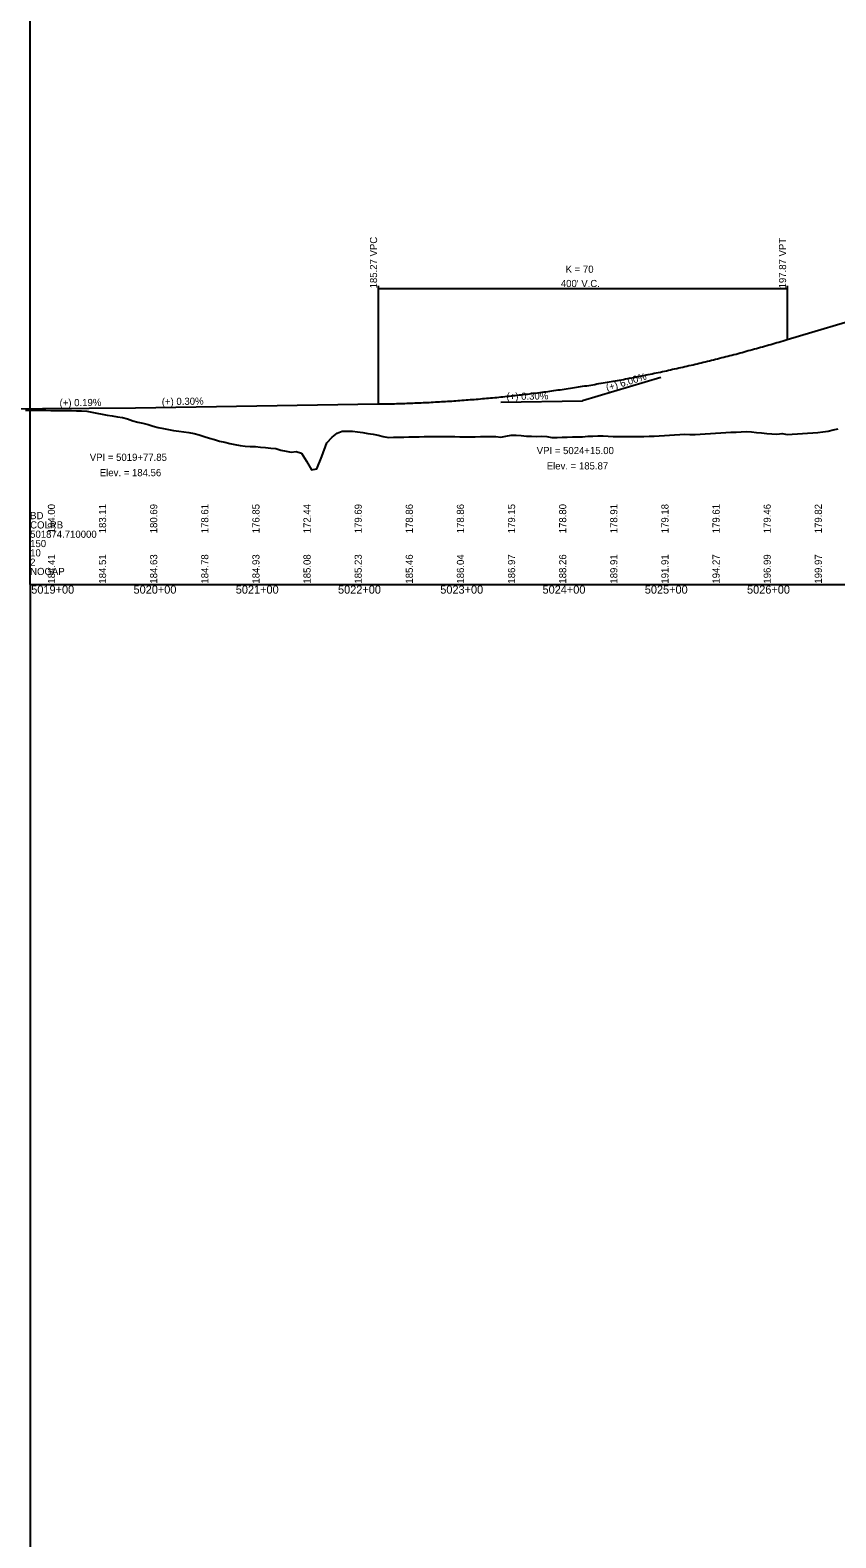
# Model space of a CAD drawing. Extents: x 1876258 to 1932803, y 754739 to 837911.
# Drawn here: x 1914544 to 1915332, y 787057 to 788531 of the extents above; entities that cross this region are included whole.
import ezdxf

# ---------------------------------------------------------------- set-up
doc = ezdxf.new("R2010")
doc.units = 0
for name, color, linetype in [('RD_DDB_GradeTX', 7, 'Continuous'), ('RD_DDB_Profile_EX', 7, 'Continuous'), ('RD_DDB_Profile_Lbl', 7, 'Continuous'), ('RD_DDB_Profile_PR', 7, 'Continuous'), ('RD_DDB_StaTX', 7, 'Continuous'), ('RD_DDB_StripGrade', 7, 'Continuous'), ('RD_DDB_VCLbl', 7, 'Continuous'), ('RD_GPK_Profile_Cell', 7, 'Continuous')]:
    doc.layers.add(name, color=color, linetype=linetype)

msp = doc.modelspace()

# ---------------------------------------------------------------- linework, layer by layer
at = {"layer": 'RD_DDB_GradeTX'}
for p in [(1915160.9, 788191.5), (1915004.3, 788167.3)]:
    msp.add_line(p, (1915084.3, 788168.5), dxfattribs=at)
at = {"layer": 'RD_DDB_Profile_EX'}
for points in [[(1914539.3, 788159.6), (1914544.3, 788159.6), (1914549.3, 788159.5), (1914554.3, 788159.5), (1914559.3, 788159.4), (1914564.3, 788159.2), (1914569.3, 788159.2), (1914574.3, 788159.1), (1914579.3, 788159), (1914584.3, 788159), (1914589.3, 788158.9), (1914594.3, 788158.8), (1914599.3, 788158.5), (1914604.3, 788157.6), (1914609.3, 788156.5), (1914614.3, 788155.6), (1914619.3, 788154.7), (1914624.3, 788154), (1914629.3, 788153.1), (1914634.3, 788152.2), (1914639.3, 788150.9), (1914644.3, 788149.1), (1914649.3, 788147.9), (1914654.3, 788146.8), (1914659.3, 788145.4), (1914664.3, 788143.8), (1914669.3, 788142.6), (1914674.3, 788141.5), (1914679.3, 788140.5), (1914684.3, 788139.7), (1914689.3, 788139), (1914694.3, 788138.3), (1914699.3, 788137.6), (1914704.3, 788136.6), (1914709.3, 788135.2), (1914714.3, 788133.7), (1914719.3, 788132.2), (1914724.3, 788130.7), (1914729.3, 788129.2), (1914734.3, 788128.1), (1914739.3, 788127), (1914744.3, 788126), (1914749.3, 788124.9), (1914754.3, 788124.2), (1914759.3, 788123.9), (1914764.3, 788123.9), (1914769.3, 788123.4), (1914774.3, 788122.9), (1914779.3, 788122.4), (1914784.3, 788121.9), (1914789.3, 788120.5), (1914794.3, 788119.5), (1914799.3, 788118.5), (1914804.3, 788119.1), (1914809.3, 788117.5), (1914814.3, 788109.7), (1914819.3, 788101.3), (1914824.3, 788102.2), (1914829.3, 788114.1), (1914834.3, 788127.5), (1914839.3, 788133.2), (1914844.3, 788136.9), (1914849.3, 788139.1), (1914854.3, 788139), (1914859.3, 788138.9), (1914864.3, 788138.4), (1914869.3, 788137.6), (1914874.3, 788136.8), (1914879.3, 788136), (1914884.3, 788135.1), (1914889.3, 788133.7), (1914894.3, 788132.9), (1914899.3, 788133), (1914904.3, 788133.1), (1914909.3, 788133.2), (1914914.3, 788133.3), (1914919.3, 788133.4), (1914924.3, 788133.5), (1914929.3, 788133.6), (1914934.3, 788133.6), (1914939.3, 788133.6), (1914944.3, 788133.7), (1914949.3, 788133.7), (1914954.3, 788133.7), (1914959.3, 788133.6), (1914964.3, 788133.4)], [(1914539.3, 788159.6), (1914544.3, 788159.6), (1914549.3, 788159.5), (1914554.3, 788159.5), (1914559.3, 788159.4), (1914564.3, 788159.2), (1914569.3, 788159.2), (1914574.3, 788159.1), (1914579.3, 788159), (1914584.3, 788159), (1914589.3, 788158.9), (1914594.3, 788158.8), (1914599.3, 788158.5), (1914604.3, 788157.6), (1914609.3, 788156.5), (1914614.3, 788155.6), (1914619.3, 788154.7), (1914624.3, 788154), (1914629.3, 788153.1), (1914634.3, 788152.2), (1914639.3, 788150.9), (1914644.3, 788149.1), (1914649.3, 788147.9), (1914654.3, 788146.8), (1914659.3, 788145.4), (1914664.3, 788143.8), (1914669.3, 788142.6), (1914674.3, 788141.5), (1914679.3, 788140.5), (1914684.3, 788139.7), (1914689.3, 788139), (1914694.3, 788138.3), (1914699.3, 788137.6), (1914704.3, 788136.6), (1914709.3, 788135.2), (1914714.3, 788133.7), (1914719.3, 788132.2), (1914724.3, 788130.7), (1914729.3, 788129.2), (1914734.3, 788128.1), (1914739.3, 788127), (1914744.3, 788126), (1914749.3, 788124.9), (1914754.3, 788124.2), (1914759.3, 788123.9), (1914764.3, 788123.9), (1914769.3, 788123.4), (1914774.3, 788122.9), (1914779.3, 788122.4), (1914784.3, 788121.9), (1914789.3, 788120.5), (1914794.3, 788119.5), (1914799.3, 788118.5), (1914804.3, 788119.1), (1914809.3, 788117.5), (1914814.3, 788109.7), (1914819.3, 788101.3), (1914824.3, 788102.2), (1914829.3, 788114.1), (1914834.3, 788127.5), (1914839.3, 788133.2), (1914844.3, 788136.9), (1914849.3, 788139.1), (1914854.3, 788139), (1914859.3, 788138.9), (1914864.3, 788138.4), (1914869.3, 788137.6), (1914874.3, 788136.8), (1914879.3, 788136), (1914884.3, 788135.1), (1914889.3, 788133.7), (1914894.3, 788132.9), (1914899.3, 788133), (1914904.3, 788133.1), (1914909.3, 788133.2), (1914914.3, 788133.3), (1914919.3, 788133.4), (1914924.3, 788133.5), (1914929.3, 788133.6), (1914934.3, 788133.6), (1914939.3, 788133.6), (1914944.3, 788133.7), (1914949.3, 788133.7), (1914954.3, 788133.7), (1914959.3, 788133.6), (1914964.3, 788133.4)], [(1914964.3, 788133.4), (1914969.3, 788133.4), (1914974.3, 788133.5), (1914979.3, 788133.5), (1914984.3, 788133.6), (1914989.3, 788133.7), (1914994.3, 788133.8), (1914999.3, 788133.6), (1915004.3, 788133.1), (1915009.3, 788134.1), (1915014.3, 788135), (1915019.3, 788134.9), (1915024.3, 788134.8), (1915029.3, 788134.1), (1915034.3, 788133.9), (1915039.3, 788133.8), (1915044.3, 788133.9), (1915049.3, 788133.7), (1915054.3, 788132.6), (1915059.3, 788132.7), (1915064.3, 788133), (1915069.3, 788133.1), (1915074.3, 788133.3), (1915079.3, 788133.4), (1915084.3, 788133.5), (1915089.3, 788134.1), (1915094.3, 788134.2), (1915099.3, 788134.3), (1915104.3, 788134.3), (1915109.3, 788134.1), (1915114.3, 788133.7), (1915119.3, 788133.7), (1915124.3, 788133.7), (1915129.3, 788133.7), (1915134.3, 788133.6), (1915139.3, 788133.7), (1915144.3, 788133.7), (1915149.3, 788134), (1915154.3, 788134.2), (1915159.3, 788134.5), (1915164.3, 788134.8), (1915169.3, 788135.1), (1915174.3, 788135.3), (1915179.3, 788135.6), (1915184.3, 788135.9), (1915189.3, 788135.6), (1915194.3, 788135.8), (1915199.3, 788136.1), (1915204.3, 788136.4), (1915209.3, 788136.7), (1915214.3, 788136.9), (1915219.3, 788137.2), (1915224.3, 788137.5), (1915229.3, 788137.8), (1915234.3, 788138), (1915239.3, 788138.3), (1915244.3, 788138.6), (1915249.3, 788138.2), (1915254.3, 788137.6), (1915259.3, 788137.2), (1915264.3, 788136.8), (1915269.3, 788136.4), (1915274.3, 788136.1), (1915279.3, 788136.8), (1915284.3, 788135.7), (1915289.3, 788136), (1915294.3, 788136.3), (1915299.3, 788136.6), (1915304.3, 788136.9), (1915309.3, 788137.2), (1915314.3, 788137.5), (1915319.3, 788138.2), (1915324.3, 788138.9), (1915329.3, 788140.1), (1915334.3, 788141.2)], [(1914964.3, 788133.4), (1914969.3, 788133.4), (1914974.3, 788133.5), (1914979.3, 788133.5), (1914984.3, 788133.6), (1914989.3, 788133.7), (1914994.3, 788133.8), (1914999.3, 788133.6), (1915004.3, 788133.1), (1915009.3, 788134.1), (1915014.3, 788135), (1915019.3, 788134.9), (1915024.3, 788134.8), (1915029.3, 788134.1), (1915034.3, 788133.9), (1915039.3, 788133.8), (1915044.3, 788133.9), (1915049.3, 788133.7), (1915054.3, 788132.6), (1915059.3, 788132.7), (1915064.3, 788133), (1915069.3, 788133.1), (1915074.3, 788133.3), (1915079.3, 788133.4), (1915084.3, 788133.5), (1915089.3, 788134.1), (1915094.3, 788134.2), (1915099.3, 788134.3), (1915104.3, 788134.3), (1915109.3, 788134.1), (1915114.3, 788133.7), (1915119.3, 788133.7), (1915124.3, 788133.7), (1915129.3, 788133.7), (1915134.3, 788133.6), (1915139.3, 788133.7), (1915144.3, 788133.7), (1915149.3, 788134), (1915154.3, 788134.2), (1915159.3, 788134.5), (1915164.3, 788134.8), (1915169.3, 788135.1), (1915174.3, 788135.3), (1915179.3, 788135.6), (1915184.3, 788135.9), (1915189.3, 788135.6), (1915194.3, 788135.8), (1915199.3, 788136.1), (1915204.3, 788136.4), (1915209.3, 788136.7), (1915214.3, 788136.9), (1915219.3, 788137.2), (1915224.3, 788137.5), (1915229.3, 788137.8), (1915234.3, 788138), (1915239.3, 788138.3), (1915244.3, 788138.6), (1915249.3, 788138.2), (1915254.3, 788137.6), (1915259.3, 788137.2), (1915264.3, 788136.8), (1915269.3, 788136.4), (1915274.3, 788136.1), (1915279.3, 788136.8), (1915284.3, 788135.7), (1915289.3, 788136), (1915294.3, 788136.3), (1915299.3, 788136.6), (1915304.3, 788136.9), (1915309.3, 788137.2), (1915314.3, 788137.5), (1915319.3, 788138.2), (1915324.3, 788138.9), (1915329.3, 788140.1), (1915334.3, 788141.2)]]:
    msp.add_lwpolyline(points, dxfattribs=at)
at = {"layer": 'RD_DDB_Profile_PR'}
for p, q in [((1915284.3, 788228.5), (1915519.3, 788299)), ((1914464.3, 788160.2), (1914647.1, 788161.9)), ((1914647.1, 788161.9), (1914884.3, 788165.5))]:
    msp.add_line(p, q, dxfattribs=at)
msp.add_spline([(1914884.3, 788165.5), (1914892.3, 788165.6), (1914900.3, 788165.8), (1914908.3, 788166.1), (1914916.3, 788166.3), (1914924.3, 788166.7), (1914932.3, 788167), (1914940.3, 788167.5), (1914948.3, 788167.9), (1914956.3, 788168.4), (1914964.3, 788169), (1914972.3, 788169.6), (1914980.3, 788170.2), (1914988.3, 788170.9), (1914996.3, 788171.6), (1915004.3, 788172.4), (1915012.3, 788173.3), (1915020.3, 788174.1), (1915028.3, 788175), (1915036.3, 788176), (1915044.3, 788177), (1915052.3, 788178.1), (1915060.3, 788179.2), (1915068.3, 788180.3), (1915076.3, 788181.5), (1915084.3, 788182.8), (1915092.3, 788184), (1915100.3, 788185.4), (1915108.3, 788186.7), (1915116.3, 788188.2), (1915124.3, 788189.6), (1915132.3, 788191.1), (1915140.3, 788192.7), (1915148.3, 788194.3), (1915156.3, 788195.9), (1915164.3, 788197.6), (1915172.3, 788199.4), (1915180.3, 788201.2), (1915188.3, 788203), (1915196.3, 788204.9), (1915204.3, 788206.8), (1915212.3, 788208.7), (1915220.3, 788210.8), (1915228.3, 788212.8), (1915236.3, 788214.9), (1915244.3, 788217.1), (1915252.3, 788219.3), (1915260.3, 788221.5), (1915268.3, 788223.8), (1915276.3, 788226.1), (1915284.3, 788228.5)], degree=3, dxfattribs=at)
at = {"layer": 'RD_DDB_VCLbl'}
for p, q in [((1914884.3, 788281), (1914884.3, 788165.5)), ((1914884.3, 788278.5), (1915284.3, 788278.5)), ((1915284.3, 788281), (1915284.3, 788228.5))]:
    msp.add_line(p, q, dxfattribs=at)
at = {"layer": 'RD_GPK_Profile_Cell'}
for q in [(1914544, 789239.1), (1916244, 787989.1), (1914544, 786739.1)]:
    msp.add_line((1914544, 787989.1), q, dxfattribs=at)

# ---------------------------------------------------------------- texts
at = {"layer": 'RD_DDB_GradeTX'}
for s, rotation, p in [('(+) 6.00%', 16.6992, (1915108.3, 788177.8)), ('(+) 0.19%', 0.5483, (1914572.8, 788163.2)), ('(+) 0.30%', 0.8594, (1914672.8, 788164.3)), ('(+) 0.30%', 0.8594, (1915009.9, 788169.4))]:
    msp.add_text(s, height=7, rotation=rotation, dxfattribs=at).set_placement(p)
at = {"layer": 'RD_DDB_Profile_Lbl'}
for s, p in [('VPI = 5019+77.85', (1914602.3, 788109.9)), ('VPI = 5024+15.00', (1915039.4, 788116.5)), ('Elev. = 184.56', (1914612.1, 788094.9)), ('Elev. = 185.87', (1915049.2, 788101.5))]:
    msp.add_text(s, height=7, dxfattribs=at).set_placement(p)
at = {"layer": 'RD_DDB_StaTX'}
for s, p in [('5019+00', (1914545.1, 787980.1)), ('5020+00', (1914645.1, 787980.1)), ('5021+00', (1914745.1, 787980.1)), ('5022+00', (1914845.1, 787980.1)), ('5023+00', (1914945.1, 787980.1)), ('5024+00', (1915045.1, 787980.1)), ('5025+00', (1915145.1, 787980.1)), ('5026+00', (1915245.1, 787980.1))]:
    msp.add_text(s, height=8, dxfattribs=at).set_placement(p)
at = {"layer": 'RD_DDB_StripGrade'}
for s, p in [('185.27 VPC', (1914883.3, 788278.5)), ('197.87 VPT', (1915283.3, 788278.5)), ('184.00', (1914568.3, 788039.1)), ('183.11', (1914618.3, 788039.1)), ('180.69', (1914668.3, 788039.1)), ('178.61', (1914718.3, 788039.1)), ('176.85', (1914768.3, 788039.1)), ('172.44', (1914818.3, 788039.1)), ('179.69', (1914868.3, 788039.1)), ('178.86', (1914918.3, 788039.1)), ('178.86', (1914968.3, 788039.1)), ('179.15', (1915018.3, 788039.1)), ('178.80', (1915068.3, 788039.1)), ('178.91', (1915118.3, 788039.1)), ('179.18', (1915168.3, 788039.1)), ('179.61', (1915218.3, 788039.1)), ('179.46', (1915268.3, 788039.1)), ('179.82', (1915318.3, 788039.1)), ('184.41', (1914568.3, 787989.9)), ('184.51', (1914618.3, 787989.9)), ('184.63', (1914668.3, 787989.9)), ('184.78', (1914718.3, 787989.9)), ('184.93', (1914768.3, 787989.9)), ('185.08', (1914818.3, 787989.9)), ('185.23', (1914868.3, 787989.9)), ('185.46', (1914918.3, 787989.9)), ('186.04', (1914968.3, 787989.9)), ('186.97', (1915018.3, 787989.9)), ('188.26', (1915068.3, 787989.9)), ('189.91', (1915118.3, 787989.9)), ('191.91', (1915168.3, 787989.9)), ('194.27', (1915218.3, 787989.9)), ('196.99', (1915268.3, 787989.9)), ('199.97', (1915318.3, 787989.9))]:
    msp.add_text(s, height=7, rotation=90, dxfattribs=at).set_placement(p)
at = {"layer": 'RD_DDB_VCLbl'}
for s, p in [('K = 70', (1915067.7, 788293.8)), ("400' V.C.", (1915063, 788279.8))]:
    msp.add_text(s, height=7, dxfattribs=at).set_placement(p)
at = {"layer": 'RD_GPK_Profile_Cell'}
for s, p in [('BD', (1914544, 788052.9)), ('501874.710000', (1914544, 788034.7)), ('COLRB', (1914544, 788043.8)), ('150', (1914544, 788025.6)), ('10', (1914544, 788016.5)), ('2', (1914544, 788007.4)), ('NOGAP', (1914544, 787998.3))]:
    msp.add_text(s, height=7, dxfattribs=at).set_placement(p)

doc.saveas('drawing.dxf')
